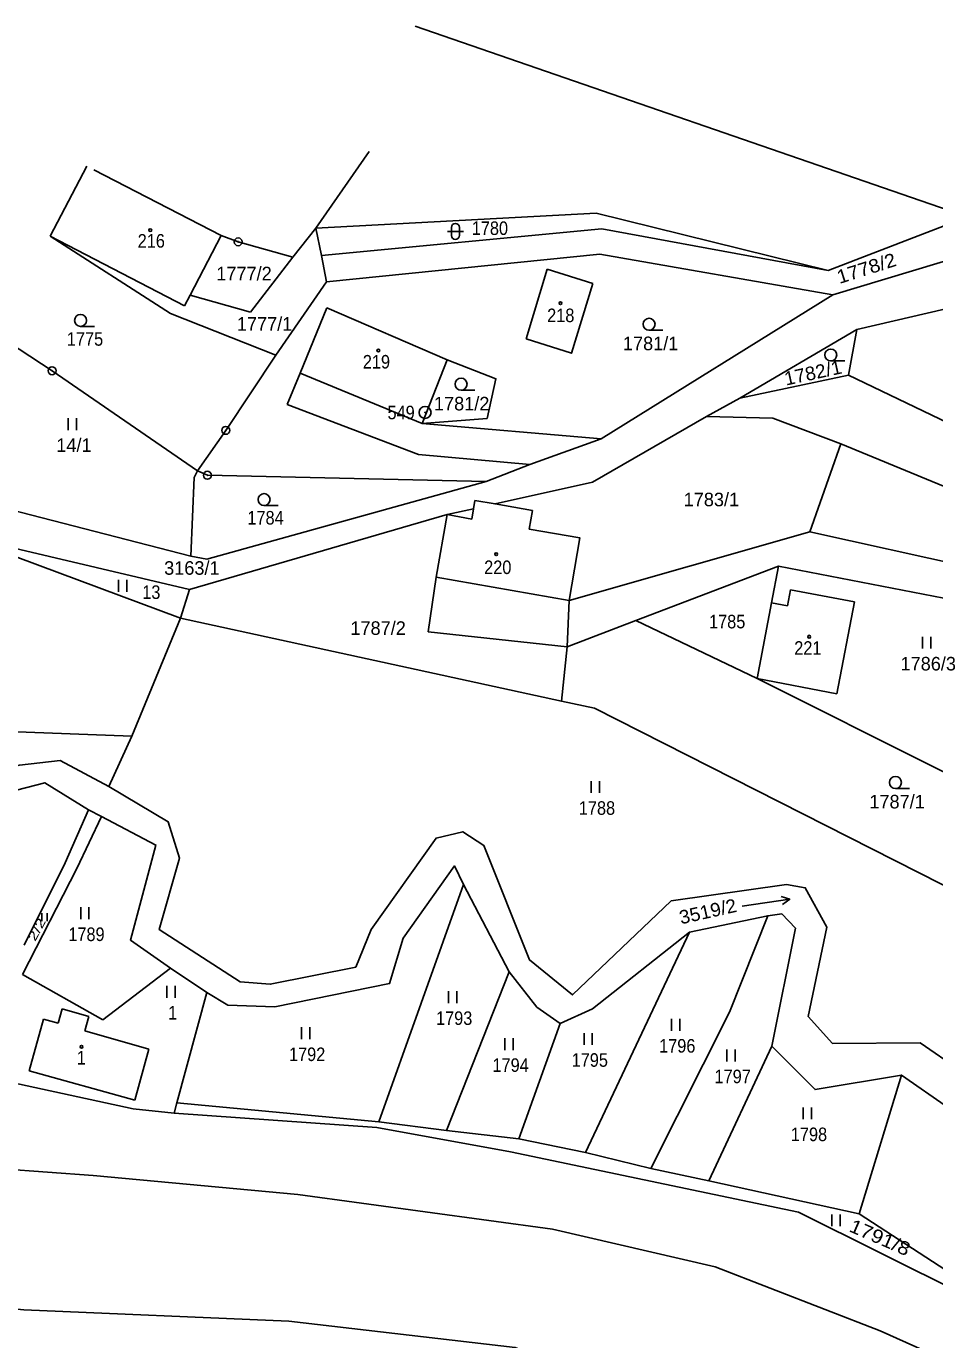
# Model space of a CAD drawing. Extents: x -665688 to -664583, y -1006118 to -1004927.
# Drawn here: x -665524.4 to -665410.4, y -1005201.6 to -1005036.9 of the extents above; entities that cross this region are included whole.
import ezdxf
from ezdxf.enums import TextEntityAlignment as Align

# ---------------------------------------------------------------- set-up
doc = ezdxf.new("R2010")
doc.units = 0
doc.header["$LTSCALE"] = 0.68
for name, color, linetype, lineweight in [('1', 7, 'Continuous', 25), ('24', 7, 'Continuous', 25), ('25', 7, 'Continuous', 25), ('4', 7, 'Continuous', 25)]:
    doc.layers.add(name, color=color, linetype=linetype, lineweight=lineweight)
for name, color, linetype in [('17', 7, 'Continuous'), ('18', 7, 'Continuous'), ('19', 7, 'Continuous')]:
    doc.layers.add(name, color=color, linetype=linetype)

msp = doc.modelspace()

# ---------------------------------------------------------------- linework, layer by layer
at = {"layer": '1'}
for p, q in [((-665521.37, -1005063.23), (-665516.79, -1005054.45)), ((-665487.34, -1005065.67), (-665452.17, -1005062.34)), ((-665452.17, -1005062.34), (-665423.81, -1005067.54)), ((-665506.28, -1005072.92), (-665521.37, -1005063.23)), ((-665521.37, -1005063.23), (-665504.53, -1005071.96)), ((-665499.95, -1005063.16), (-665497.8, -1005063.95)), ((-665490.95, -1005065.89), (-665496.26, -1005072.76)), ((-665486.73, -1005068.98), (-665452.42, -1005065.49)), ((-665452.42, -1005065.49), (-665423.21, -1005070.61)), ((-665403.89, -1005064.79), (-665423.21, -1005070.61)), ((-665459.04, -1005067.39), (-665461.69, -1005076.13)), ((-665453.33, -1005069.17), (-665459.04, -1005067.39)), ((-665493.09, -1005078.16), (-665486.73, -1005068.98)), ((-665496.26, -1005072.76), (-665503.84, -1005070.63)), ((-665452.26, -1005088.67), (-665423.21, -1005070.61)), ((-665403.06, -1005070.95), (-665420.2, -1005074.94)), ((-665532.44, -1005072.72), (-665521.14, -1005080.12)), ((-665486.66, -1005072.24), (-665490.04, -1005080.41)), ((-665486.66, -1005072.24), (-665471.59, -1005078.74)), ((-665420.2, -1005074.94), (-665421.27, -1005080.68)), ((-665471.59, -1005078.74), (-665474.74, -1005086.75)), ((-665490.04, -1005080.41), (-665491.67, -1005084.35)), ((-665434.88, -1005083.57), (-665421.27, -1005080.68)), ((-665397.04, -1005092.31), (-665421.27, -1005080.68)), ((-665475.19, -1005090.64), (-665491.67, -1005084.35)), ((-665439.07, -1005085.87), (-665453.34, -1005094.08)), ((-665466.59, -1005086.1), (-665474.74, -1005086.75)), ((-665452.26, -1005088.67), (-665474.74, -1005086.75)), ((-665430.76, -1005086.08), (-665422.23, -1005089.3)), ((-665461.23, -1005091.86), (-665452.26, -1005088.67)), ((-665426.11, -1005100.32), (-665422.23, -1005089.3)), ((-665422.23, -1005089.3), (-665335.95, -1005124.81)), ((-665503.75, -1005103.38), (-665503.3, -1005093.51)), ((-665503.3, -1005093.51), (-665502.92, -1005092.65)), ((-665501.74, -1005103.75), (-665466.7, -1005094)), ((-665453.34, -1005094.08), (-665465.58, -1005096.82)), ((-665471.59, -1005098.16), (-665503.92, -1005107.53)), ((-665460.9, -1005097.65), (-665461.31, -1005099.99)), ((-665503.75, -1005103.38), (-665501.74, -1005103.75)), ((-665447.94, -1005111.43), (-665430.02, -1005104.62)), ((-665430.02, -1005104.62), (-665430.9, -1005109.2)), ((-665430.02, -1005104.62), (-665382.13, -1005113.93)), ((-665428.91, -1005109.58), (-665428.53, -1005107.57)), ((-665428.53, -1005107.57), (-665420.5, -1005109.11)), ((-665430.9, -1005109.2), (-665432.72, -1005118.7)), ((-665430.9, -1005109.2), (-665428.91, -1005109.58)), ((-665420.5, -1005109.11), (-665422.71, -1005120.62)), ((-665456.55, -1005114.73), (-665447.94, -1005111.43)), ((-665432.72, -1005118.7), (-665447.94, -1005111.43)), ((-665456.55, -1005114.73), (-665457.24, -1005121.53)), ((-665422.71, -1005120.62), (-665432.72, -1005118.7)), ((-665453.12, -1005122.43), (-665374.45, -1005162.35)), ((-665514.96, -1005136.01), (-665516.57, -1005135.18)), ((-665518.03, -1005142.52), (-665514.96, -1005136.01)), ((-665524.85, -1005155.81), (-665518.03, -1005142.52)), ((-665480.17, -1005174.3), (-665469.55, -1005144.54)), ((-665454.25, -1005178.14), (-665441.2, -1005150.52)), ((-665514.79, -1005161.53), (-665506.28, -1005155.04)), ((-665524.85, -1005155.81), (-665514.79, -1005161.53)), ((-665463.81, -1005155.49), (-665471.68, -1005175.38)), ((-665501.74, -1005158.09), (-665505.49, -1005171.9)), ((-665524.01, -1005167.92), (-665522.22, -1005161.42)), ((-665522.22, -1005161.42), (-665520.39, -1005161.94)), ((-665519.87, -1005160.12), (-665520.39, -1005161.94)), ((-665516.51, -1005161.08), (-665519.87, -1005160.12)), ((-665517.03, -1005162.9), (-665516.51, -1005161.08)), ((-665517.03, -1005162.9), (-665508.99, -1005165.2)), ((-665457.42, -1005161.99), (-665462.61, -1005176.43)), ((-665430.88, -1005164.83), (-665438.75, -1005181.72)), ((-665510.75, -1005171.58), (-665508.99, -1005165.2)), ((-665510.75, -1005171.58), (-665524.01, -1005167.92)), ((-665419.93, -1005185.83), (-665414.61, -1005168.44)), ((-665505.49, -1005171.9), (-665505.84, -1005173.21)), ((-665505.84, -1005173.21), (-665480.43, -1005175.02))]:
    msp.add_line(p, q, dxfattribs=at)
for points in [[(-665391.59, -1005056.15), (-665406.32, -1005060.8), (-665475.6, -1005036.92)], [(-665452.92, -1005060.35), (-665488.06, -1005062.22), (-665481.38, -1005052.64)], [(-665406.32, -1005060.8), (-665423.81, -1005067.54), (-665452.92, -1005060.35)], [(-665497.8, -1005063.95), (-665490.95, -1005065.89), (-665488.06, -1005062.22)], [(-665488.06, -1005062.22), (-665487.34, -1005065.67), (-665486.73, -1005068.98)], [(-665504.53, -1005071.96), (-665503.84, -1005070.63), (-665499.95, -1005063.16)], [(-665453.33, -1005069.17), (-665455.99, -1005077.93), (-665461.69, -1005076.13)], [(-665499.35, -1005087.59), (-665493.09, -1005078.16), (-665506.28, -1005072.92)], [(-665420.2, -1005074.94), (-665434.88, -1005083.57), (-665439.07, -1005085.87), (-665430.76, -1005086.08)], [(-665471.59, -1005078.74), (-665465.48, -1005081.13), (-665466.59, -1005086.1)], [(-665521.14, -1005080.12), (-665502.92, -1005092.65), (-665499.35, -1005087.59)], [(-665466.7, -1005094), (-665461.23, -1005091.86), (-665475.19, -1005090.64)], [(-665535.98, -1005092.65), (-665531.82, -1005096.14), (-665503.75, -1005103.38)], [(-665466.7, -1005094), (-665501.66, -1005093.22), (-665502.92, -1005092.65)], [(-665544.94, -1005094.79), (-665533.23, -1005100.65), (-665505.02, -1005111.13), (-665511.14, -1005125.96)], [(-665468.1, -1005096.37), (-665468.28, -1005097.42), (-665471.59, -1005098.16)], [(-665468.1, -1005096.37), (-665465.58, -1005096.82), (-665460.9, -1005097.65)], [(-665471.59, -1005098.16), (-665472.96, -1005106), (-665473.99, -1005112.84)], [(-665505.02, -1005111.13), (-665503.92, -1005107.53), (-665533.23, -1005100.65)], [(-665461.31, -1005099.99), (-665454.93, -1005101.07), (-665456.3, -1005108.91)], [(-665386.07, -1005109.18), (-665426.11, -1005100.32), (-665456.3, -1005108.91)], [(-665473.99, -1005112.84), (-665456.55, -1005114.73), (-665456.3, -1005108.91)], [(-665505.02, -1005111.13), (-665457.24, -1005121.53), (-665453.12, -1005122.43)], [(-665543.3, -1005118.41), (-665534.37, -1005125.08), (-665511.14, -1005125.96), (-665514.04, -1005132.26), (-665520.11, -1005128.99), (-665525.24, -1005129.57), (-665538.58, -1005132.69)], [(-665432.72, -1005118.7), (-665410.01, -1005130.09), (-665384.16, -1005143.05), (-665368.06, -1005151.13)], [(-665564.22, -1005148.26), (-665552.71, -1005146.21), (-665543.25, -1005137.26), (-665522.06, -1005131.79), (-665516.57, -1005135.18)], [(-665514.04, -1005132.26), (-665506.59, -1005136.67), (-665505.17, -1005141.25), (-665507.72, -1005150.19), (-665497.57, -1005156.74), (-665493.78, -1005157.05), (-665483.06, -1005154.9), (-665481.11, -1005150.18), (-665472.97, -1005138.71), (-665469.63, -1005137.92), (-665466.97, -1005139.63), (-665461.25, -1005154), (-665455.88, -1005158.39), (-665443.5, -1005146.6), (-665429.04, -1005144.56), (-665426.68, -1005144.95), (-665423.98, -1005149.89), (-665426.32, -1005161.08), (-665423.25, -1005164.48), (-665412.28, -1005164.4), (-665397.32, -1005174.67), (-665385.41, -1005181.4)], [(-665516.57, -1005135.18), (-665519.49, -1005141.81), (-665524.66, -1005152.15)], [(-665386.94, -1005183.97), (-665408.69, -1005172.54), (-665414.61, -1005168.44), (-665425.44, -1005170.25), (-665430.88, -1005164.83), (-665427.9, -1005150.02), (-665429.63, -1005148.23), (-665431.37, -1005148.46), (-665441.2, -1005150.52), (-665453.34, -1005160.14), (-665457.42, -1005161.99), (-665460.34, -1005159.94), (-665463.81, -1005155.49), (-665469.55, -1005144.54), (-665470.65, -1005142.21), (-665477.11, -1005151.29), (-665478.82, -1005156.97), (-665493.22, -1005159.88), (-665499.08, -1005159.69), (-665501.74, -1005158.09), (-665506.28, -1005155.04), (-665511.31, -1005151.51), (-665508.11, -1005139.59), (-665514.96, -1005136.01)], [(-665446.06, -1005180.15), (-665436.16, -1005160.55), (-665431.37, -1005148.46)], [(-665593.42, -1005154.98), (-665590.17, -1005156.55), (-665581.14, -1005160.82), (-665545.66, -1005172.05), (-665527.86, -1005181.07), (-665527.45, -1005180.2), (-665515.99, -1005181.03), (-665490.32, -1005183.42), (-665458.39, -1005187.75), (-665437.98, -1005192.49), (-665417.3, -1005200.53), (-665399.75, -1005208.35)], [(-665531.25, -1005168.29), (-665510.97, -1005172.68), (-665505.84, -1005173.21)], [(-665427.51, -1005185.63), (-665396.36, -1005201.13), (-665419.93, -1005185.83), (-665438.75, -1005181.72), (-665446.06, -1005180.15), (-665454.25, -1005178.14), (-665462.61, -1005176.43), (-665471.68, -1005175.38), (-665480.17, -1005174.3), (-665505.49, -1005171.9)], [(-665480.43, -1005175.02), (-665463.65, -1005178.05), (-665427.51, -1005185.63)], [(-665606.44, -1005185.69), (-665588.29, -1005189.45), (-665568.47, -1005193.44), (-665524.68, -1005197.88), (-665491.46, -1005199.28), (-665463.07, -1005202.62), (-665454.32, -1005206.34), (-665437.29, -1005211.76), (-665406.05, -1005224.73)]]:
    msp.add_lwpolyline(points, dxfattribs=at)
at = {"layer": '24'}
for centre, radius in [((-665497.8, -1005063.95), 0.5), ((-665497.8, -1005063.95), 0.032), ((-665521.14, -1005080.12), 0.5), ((-665521.14, -1005080.12), 0.032), ((-665474.36, -1005085.35), 0.75), ((-665474.36, -1005085.35), 0.032), ((-665499.35, -1005087.59), 0.5), ((-665499.35, -1005087.59), 0.032), ((-665501.66, -1005093.22), 0.5), ((-665501.66, -1005093.22), 0.032)]:
    msp.add_circle(centre, radius, dxfattribs=at)
at = {"layer": '25'}
for p, q in [((-665471.56, -1005062.65), (-665469.56, -1005062.65)), ((-665471.06, -1005063.15), (-665471.06, -1005062.15)), ((-665470.06, -1005062.15), (-665470.06, -1005063.15)), ((-665517.57, -1005074.55), (-665515.82, -1005074.55)), ((-665446.27, -1005075.04), (-665444.52, -1005075.04)), ((-665423.47, -1005078.89), (-665421.72, -1005078.89)), ((-665469.85, -1005082.55), (-665468.1, -1005082.55)), ((-665519.117, -1005087.565), (-665519.117, -1005086.065)), ((-665518.083, -1005087.565), (-665518.083, -1005086.065)), ((-665494.55, -1005097.02), (-665492.8, -1005097.02)), ((-665512.797, -1005107.845), (-665512.797, -1005106.345)), ((-665511.763, -1005107.845), (-665511.763, -1005106.345)), ((-665411.967, -1005114.965), (-665411.967, -1005113.465)), ((-665410.933, -1005114.965), (-665410.933, -1005113.465)), ((-665453.517, -1005133.065), (-665453.517, -1005131.565)), ((-665452.483, -1005133.065), (-665452.483, -1005131.565)), ((-665415.36, -1005132.5), (-665413.61, -1005132.5)), ((-665434.569, -1005147.247), (-665428.631, -1005146.393)), ((-665522.436, -1005149.122), (-665522.436, -1005148.117)), ((-665521.743, -1005149.122), (-665521.743, -1005148.117)), ((-665517.547, -1005148.895), (-665517.547, -1005147.395)), ((-665516.513, -1005148.895), (-665516.513, -1005147.395)), ((-665506.737, -1005158.735), (-665506.737, -1005157.235)), ((-665505.703, -1005158.735), (-665505.703, -1005157.235)), ((-665471.427, -1005159.415), (-665471.427, -1005157.915)), ((-665470.393, -1005159.415), (-665470.393, -1005157.915)), ((-665443.447, -1005162.885), (-665443.447, -1005161.385)), ((-665442.413, -1005162.885), (-665442.413, -1005161.385)), ((-665489.867, -1005163.945), (-665489.867, -1005162.445)), ((-665488.833, -1005163.945), (-665488.833, -1005162.445)), ((-665454.417, -1005164.665), (-665454.417, -1005163.165)), ((-665453.383, -1005164.665), (-665453.383, -1005163.165)), ((-665464.347, -1005165.305), (-665464.347, -1005163.805)), ((-665463.313, -1005165.305), (-665463.313, -1005163.805)), ((-665436.497, -1005166.725), (-665436.497, -1005165.225)), ((-665435.463, -1005166.725), (-665435.463, -1005165.225)), ((-665426.927, -1005173.985), (-665426.927, -1005172.485)), ((-665425.893, -1005173.985), (-665425.893, -1005172.485)), ((-665423.327, -1005187.405), (-665423.327, -1005185.905)), ((-665422.293, -1005187.405), (-665422.293, -1005185.905))]:
    msp.add_line(p, q, dxfattribs=at)
msp.add_lwpolyline([(-665429.692, -1005146.04), (-665428.631, -1005146.393), (-665429.55, -1005147.029)], dxfattribs=at)
for centre, radius in [((-665508.82, -1005062.48), 0.175), ((-665457.38, -1005071.65), 0.175), ((-665517.57, -1005073.8), 0.75), ((-665446.27, -1005074.29), 0.75), ((-665480.22, -1005077.58), 0.175), ((-665423.47, -1005078.14), 0.75), ((-665469.85, -1005081.8), 0.75), ((-665494.55, -1005096.27), 0.75), ((-665465.44, -1005103.11), 0.175), ((-665426.18, -1005113.47), 0.175), ((-665415.36, -1005131.75), 0.75), ((-665517.44, -1005164.89), 0.175)]:
    msp.add_circle(centre, radius, dxfattribs=at)
for centre, start, end in [((-665470.56, -1005062.15), 0.101, 180.00143), ((-665470.56, -1005063.15), 180.10243, 0.00286)]:
    msp.add_arc(centre, 0.5, start, end, dxfattribs=at)
at = {"layer": '4'}
for p, q in [((-665499.95, -1005063.16), (-665515.91, -1005054.91)), ((-665490.04, -1005080.41), (-665474.74, -1005086.75)), ((-665468.28, -1005097.42), (-665468.5, -1005098.71)), ((-665471.59, -1005098.16), (-665468.5, -1005098.71)), ((-665472.96, -1005106), (-665456.3, -1005108.91))]:
    msp.add_line(p, q, dxfattribs=at)

# ---------------------------------------------------------------- texts
at = {"layer": '17', "width": 0.9}
msp.add_text('549', height=1.7, dxfattribs=at).set_placement((-665475.66, -1005086.2), align=Align.RIGHT)
at = {"layer": '18', "width": 0.9}
for s, p in [('1780', (-665466.2295, -1005063.09)), ('1775', (-665517.0095, -1005076.98)), ('1784', (-665494.3695, -1005099.4)), ('13', (-665508.69, -1005108.73)), ('1785', (-665436.4695, -1005112.42)), ('1788', (-665452.7995, -1005135.8)), ('1789', (-665516.8295, -1005151.63)), ('1', (-665506.0195, -1005161.47)), ('1793', (-665470.7095, -1005162.15)), ('1792', (-665489.1495, -1005166.68)), ('1796', (-665442.7295, -1005165.62)), ('1794', (-665463.6295, -1005168.04)), ('1795', (-665453.6995, -1005167.4)), ('1797', (-665435.7795, -1005169.46)), ('1798', (-665426.2095, -1005176.72))]:
    msp.add_text(s, height=1.7, dxfattribs=at).set_placement(p, align=Align.CENTER)
at = {"layer": '18'}
for s, height, rotation, width, p in [('1778/2', 1.7, 17.7, 1.1, (-665418.7479, -1005068.08)), ('1782/1', 1.7, 12.3, 1.05, (-665425.5256, -1005081.2062)), ('3519/2', 1.7, 12.7, 1.05, (-665438.7069, -1005148.7406)), ('2/2', 1.14, 61.9, 1.4, (-665522.5627, -1005150.442)), ('1791/8', 1.7, 336.503, 1.15, (-665417.6409, -1005189.5828))]:
    msp.add_text(s, height=height, rotation=rotation, dxfattribs=dict(at, width=width)).set_placement(p, align=Align.CENTER)
for s, p in [('1777/2', (-665497.0695, -1005068.78)), ('1777/1', (-665494.4895, -1005075.09)), ('1781/1', (-665446.0695, -1005077.54)), ('1781/2', (-665469.7695, -1005085.09)), ('14/1', (-665518.3995, -1005090.3)), ('1783/1', (-665438.4495, -1005097.11)), ('3163/1', (-665503.6095, -1005105.7)), ('1787/2', (-665480.2495, -1005113.24)), ('1786/3', (-665411.2495, -1005117.7)), ('1787/1', (-665415.1595, -1005135))]:
    msp.add_text(s, height=1.7, dxfattribs=at).set_placement(p, align=Align.CENTER)
at = {"layer": '19', "width": 0.9}
for s, p in [('216', (-665508.6995, -1005064.68)), ('218', (-665457.3395, -1005074.02)), ('219', (-665480.4595, -1005079.84)), ('220', (-665465.2395, -1005105.61)), ('221', (-665426.3495, -1005115.73)), ('1', (-665517.4795, -1005167.12))]:
    msp.add_text(s, height=1.7, dxfattribs=at).set_placement(p, align=Align.CENTER)

doc.saveas('drawing.dxf')
